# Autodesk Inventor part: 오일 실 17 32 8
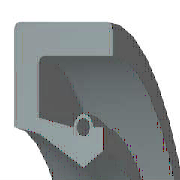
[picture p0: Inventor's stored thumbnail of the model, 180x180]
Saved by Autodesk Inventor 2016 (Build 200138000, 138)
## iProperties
IsCustomPart: 1
Created: 2012-02
Part Number: 오일 실 17 32 8
Material: 고무
Description: 오일-실
Document SubType Name: Modeling
Standard: KS B 2804
Designer: test
Standards Organization: KS
Language: ko-KR
Size Designation: S - 17 32 8
Categories: <MemberInstance><Categories><Category DisplayName="샤프트 부품" InternalName="7f7aeb1f-a693-4053-b835-cee3144e0d98" Mnemonic="SHFT"><Category DisplayName="실링" Intern
Density: 0.93 g/cm^3
Appearance: 고무 - 검은색 - 버전 1.1
Mass: 1.89534 g
Surface Area: 30.829 cm^2
Volume: 2.038 cm^3
Author: test
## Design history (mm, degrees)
revolve "본체" stored, may be unused: angle "d17" = 90 deg
revolve "스프링1" stored, may be unused: angle "d18" = 90 deg
body "Solid1"
sketch "스케치1"
  geometry: L1 (0, 16)-(8, 16); L2 (8, 16)-(8, 14.75); L3 (8, 14.75)-(1.75, 14.75); L4 (0, 16)-(0, 10.6); L5 (0, 10.6)-(1.75, 10.25); L6 (1.75, 10.25)-(4.9, 8.5); L7 (4.9, 8.5)-(0, 8.5); L8 (6.3, 9.375)-(6.3, 10.6); L9 (0, 0)-(9.586, 0) reference; L10 (4.9, 8.5)-(6.3, 9.375); L11 (0, 18)-(0, -3) reference; L12 (-1.917, 0)-(11.503, 0) reference; L13 (4.2, 10.6)-(1.75, 11.09); L14 (1.75, 11.09)-(1.75, 14.75); L15 (6.3, 10.6)-(5.6, 10.6); C1 r 0.455 at (4.9, 10.6); A1 r 0.7 centre (4.9, 10.6) between (5.6, 10.6) and (4.2, 10.6)
  constraints: 26 end point, 5 horizontal alignment, 4 perpendicular, 2 centre point, 2 collinear, 2 horizontal, 2 parallel, 2 point on circle, 2 point on line, 2 vertical alignment, 1 coincident
  dimensions: "d0" = 32 diameter of L1 L9 (= SD2); "d1" = 18.75 diameter of L8.start L9 (= ABDM); "d2" = 1.25 distance of L1.end L2.end (computed from SD); "d3" = 0.91 diameter of C1 (= SPDI); "d4" = 1.4 diameter of A1 (= SPDA); "d5" = 17 diameter of L6.end L9 (= NND); "d6" = 20.5 diameter of L5.end L9 (= TKDM); "d7" = 21.2 diameter of L4.end L9 (= HLDM); "d8" = 4.9 distance from line of C1.centre L4 (= SPDST); "d9" = 6.3 distance between parallel lines of L8 L4 (= SDI); "d10" = 8 distance between parallel lines of L2 L4 (= SWDT); "d12" = 1.75 distance between parallel lines of L14 L4 (= SD)
fillet "모깎기1" dims "d11" = 0.3 (= RR)
other parameters: "SD2" = 32 [user parameter; used in 1 equation term], "SWDT" = 8 [user parameter; used in 1 equation term], "RR" = 0.3 [user parameter; used in 1 equation term], "SD" = 1.75 [user parameter; used in 2 equation terms], "NND" = 17 [user parameter; used in 1 equation term], "SPDA" = 1.4 [user parameter; used in 1 equation term], "SPDI" = 0.91 [user parameter; used in 1 equation term], "TKDM" = 20.5 [user parameter; used in 1 equation term], "HLDM" = 21.2 [user parameter; used in 1 equation term], "ABDM" = 18.75 [user parameter; used in 1 equation term], "SDI" = 6.3 [user parameter; used in 1 equation term], "SPDST" = 4.9 [user parameter; used in 1 equation term], "d13" = 0, "d14" = 0, "d15" = 0, "LAB" = 0.35 [user parameter]
